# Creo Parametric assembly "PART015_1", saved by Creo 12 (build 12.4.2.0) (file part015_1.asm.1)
Units: Custom; MM, KILOGRAM, SECS

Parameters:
  PTC_WM_ITERATION = "0"
  PTC_WM_VERSION = "-.0"
  PTC_WM_LIFECYCLE_STATE = "In Work"
  PTC_WM_LIFECYCLE = "MO_CADDocument"
  PTC_WM_CREATED_BY = "Maximilian Roepper (Z0017RMS: MO)"
  PTC_WM_CREATED_ON = "18-Sep-26 11:36:42 AM"
  PTC_WM_MODIFIED_BY = "Maximilian Roepper (Z0017RMS: MO)"
  PTC_WM_MODIFIED_ON = "18-Sep-26 11:36:46 AM"
  PDMLINKNUMBER = "PDM000071455294"
  PTC_WM_NUMBER = "PDM000071455294"

Other parameters: WEIGHT, WEIGHT_FACTOR, WEIGHT_ADD, MC_ERRORS, SUPPLIER

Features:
  1. coordinate system
  2. imported feature
  3. component "SHAPESTRING262_1"

Other named items: DRW_VIEW_ORG, ROUGH-GROB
